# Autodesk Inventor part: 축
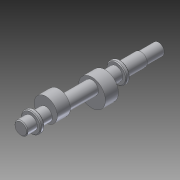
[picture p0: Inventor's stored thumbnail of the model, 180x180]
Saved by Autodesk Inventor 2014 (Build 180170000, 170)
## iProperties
Created: 2014-12
Part Number: 축
Material: 알루미늄 6061
Document SubType Name: Modeling
Designer: Owner
Density: 2.71 g/cm^3
Appearance: 알루미늄 - 평지
Mass: 170.354 g
Surface Area: 153.402 cm^2
Volume: 62.8614 cm^3
Author: Owner
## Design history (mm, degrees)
sketch "스케치1"
  geometry: C1 r 8.5 at (0, 0); 1 further point
  constraints: 1 centre point, 1 coincident
  dimensions: "d0" = 17 diameter of C1
extrude "돌출1" new body sketch "스케치1" distance "d1" = 13; taper "d2" = 0 deg
sketch "스케치2"
  geometry: C1 r 8.5 at (0, 0) reference; C2 r 13 at (0, 0)
  constraints: 1 centre point, 1 coincident
  dimensions: "d3" = 26 diameter of C2
extrude "돌출2" join sketch "스케치2" distance "d4" = 5; taper "d5" = 0 deg
sketch "스케치3"
  geometry: C1 r 13 at (0, 0) reference; C2 r 8.5 at (0, 0)
  constraints: 1 centre point, 1 coincident
  dimensions: "d6" = 17 diameter of C2
extrude "돌출3" join sketch "스케치3" distance "d7" = 14.5; taper "d8" = 0 deg
sketch "스케치4"
  geometry: C1 r 8.5 at (0, 0) reference; C2 r 15 at (0, -5); 1 further point
  constraints: 1 centre point, 1 coincident, 1 vertical alignment
  dimensions: "d9" = 5 distance of C1.centre point (0, -5); "d10" = 30 diameter of C2
extrude "돌출4" join sketch "스케치4" distance "d11" = 17; taper "d12" = 0 deg
sketch "스케치5"
  geometry: C1 r 8.5 at (0, 5); 1 further point
  constraints: 1 centre point, 1 coincident
  dimensions: "d13" = 17 diameter of C1
extrude "돌출5" join sketch "스케치5" distance "d14" = 43; taper "d15" = 0 deg
sketch "스케치6"
  geometry: C1 r 8.5 at (0, 0) reference; C2 r 17.5 at (0, 6); 1 further point
  constraints: 1 centre point, 1 coincident, 1 vertical alignment
  dimensions: "d16" = 6 distance of C1.centre point (0, 6); "d17" = 35 diameter of C2
extrude "돌출6" join sketch "스케치6" distance "d18" = 17; taper "d19" = 0 deg
sketch "스케치7"
  geometry: C1 r 8.5 at (0, -6); 1 further point
  constraints: 1 centre point, 1 coincident
  dimensions: "d20" = 17 diameter of C1
extrude "돌출7" join sketch "스케치7" distance "d21" = 14.5; taper "d22" = 0 deg
sketch "스케치8"
  geometry: C1 r 8.5 at (0, 0) reference; C2 r 13 at (0, 0)
  constraints: 1 centre point, 1 coincident
  dimensions: "d23" = 26 diameter of C2
extrude "돌출8" join sketch "스케치8" distance "d24" = 5; taper "d25" = 0 deg
sketch "스케치9"
  geometry: C1 r 13 at (0, 0) reference; C2 r 8.5 at (0, 0)
  constraints: 1 centre point, 1 coincident
  dimensions: "d26" = 17 diameter of C2
extrude "돌출9" join sketch "스케치9" distance "d27" = 27; taper "d28" = 0 deg
sketch "스케치10"
  geometry: C1 r 8.5 at (0, 0) reference; C2 r 7.5 at (0, 0)
  constraints: 1 centre point, 1 coincident
  dimensions: "d29" = 15 diameter of C2
extrude "돌출10" join sketch "스케치10" distance "d30" = 24; taper "d31" = 0 deg
node "작업 평면1"
sketch "스케치11"
  geometry: L1 (7.5, 24)-(-7.5, 24) reference; L2 (7.5, 24)-(-7.5, 24) reference; L3 (-7.5, 0)-(7.5, 0) reference; L4 (7.5, 0)-(7.5, 24) reference; L5 (-7.5, 0)-(-7.5, 24) reference; L6 (-2.5, 24)-(-2.5, 6.5); L7 (2.5, 24)-(2.5, 6.5); L8 (-2.5, 24)-(2.5, 24); A1 r 2.5 centre (0, 6.5) between (-2.5, 6.5) and (2.5, 6.5); 2 further points
  constraints: 6 end point, 2 parallel, 2 point on circle, 2 point on line, 2 tangent, 1 centre point, 1 collinear, 1 midpoint, 1 vertical alignment
  dimensions: "d32" = 5 diameter of A1; "d33" = 20 dimension on A1 L1
extrude "돌출11" cut sketch "스케치11" distance "d34" = 3; taper "d35" = 0 deg
chamfer "모따기1" distance "d36" = 1; stored, may be unused: second distance "d37" = 2, angle "d38" = 45 deg
chamfer "모따기2" distance "d39" = 1; stored, may be unused: second distance "d40" = 2, angle "d41" = 45 deg
chamfer "모따기3" distance "d42" = 1; stored, may be unused: second distance "d43" = 2, angle "d44" = 45 deg
chamfer "모따기4" distance "d45" = 1; stored, may be unused: second distance "d46" = 2, angle "d47" = 45 deg
chamfer "모따기5" distance "d48" = 1; stored, may be unused: second distance "d49" = 2, angle "d50" = 45 deg
chamfer "모따기6" distance "d51" = 1; stored, may be unused: second distance "d52" = 2, angle "d53" = 45 deg
node "솔리드1"
node "투영된 루프1"
